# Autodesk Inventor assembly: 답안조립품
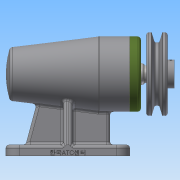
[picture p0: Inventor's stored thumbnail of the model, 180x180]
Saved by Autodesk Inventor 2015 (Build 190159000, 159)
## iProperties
Created: 2018-09
Part Number: 답안조립품
Document SubType Name: Assembly
Designer: user
Author: user
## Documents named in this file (12)
- C:\Users\user\Desktop\480907V1005\답안조립품.iam
- C:\Users\user\Desktop\480907V1005\본체.ipt
- C:\Users\user\Desktop\480907V1005\커버.ipt
- C:\Users\user\Desktop\480907V1005\축.ipt
- C:\Users\user\Desktop\480907V1005\베어링 6004.ipt
- C:\Users\user\Desktop\480907V1005\어댑터슬리브.ipt
- C:\Users\user\Desktop\480907V1005\베어링 51202.ipt
- C:\Users\user\Desktop\480907V1005\오일 실.ipt
- C:\Users\user\Desktop\480907V1005\키 5 x 5 x 16.ipt
- C:\Users\user\Desktop\480907V1005\V벨트풀리.ipt
- C:\Users\user\Desktop\480907V1005\멈춤나사 M3.ipt
- C:\Users\user\Desktop\480907V1005\볼트 M4.ipt
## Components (1 placed, 1 different names)
1. V벨트풀리:1 — 각도:2
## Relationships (1: Angle 1)
- 각도:2 [Angle]: V벨트풀리:1
